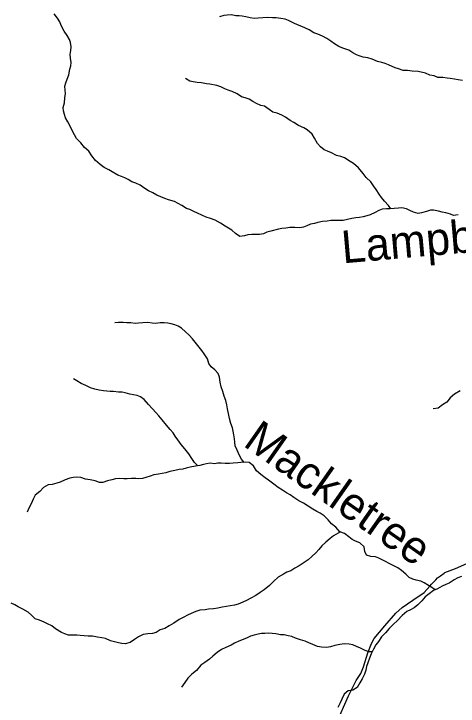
# Model space of a CAD drawing. Extents: x 0 to 34, y 0 to 22.
# Drawn here: x 3.475 to 4.768, y 15.178 to 17.193 of the extents above; entities that cross this region are included whole.
import ezdxf

# ---------------------------------------------------------------- set-up
doc = ezdxf.new("R2010")
doc.units = 0
for name, color, linetype in [('GM_X_Minor_River', 7, 'Continuous'), ('GM_X_Minor_River_Text', 7, 'Continuous'), ('GM_X_Township_Road', 7, 'Continuous')]:
    doc.layers.add(name, color=color, linetype=linetype)

msp = doc.modelspace()

# ---------------------------------------------------------------- linework, layer by layer
at = {"layer": 'GM_X_Minor_River'}
for points in [[(3.8433, 16.694), (3.8304, 16.6998), (3.8191, 16.704), (3.8081, 16.7102), (3.7986, 16.7152), (3.7884, 16.719), (3.7777, 16.7233), (3.7618, 16.7328), (3.7516, 16.7382), (3.738, 16.7455), (3.7262, 16.7543), (3.7134, 16.7662), (3.7021, 16.7791), (3.6938, 16.7925), (3.6809, 16.8036), (3.67, 16.8173), (3.6575, 16.8299), (3.6519, 16.8402), (3.6447, 16.8531), (3.638, 16.8672), (3.6327, 16.8779), (3.6256, 16.8901), (3.6226, 16.9), (3.62, 16.9106), (3.6193, 16.9201), (3.6224, 16.9338), (3.6241, 16.9486), (3.6257, 16.9607), (3.6246, 16.9706), (3.6239, 16.982), (3.6266, 16.9922), (3.6301, 17.0021), (3.6351, 17.0149), (3.6379, 17.0313), (3.6414, 17.0415), (3.6422, 17.0514), (3.6407, 17.0635), (3.6389, 17.0745), (3.6409, 17.0863), (3.6421, 17.0969), (3.6403, 17.1087), (3.6369, 17.1182), (3.6305, 17.1293), (3.6222, 17.1426), (3.6132, 17.1586), (3.6087, 17.1697), (3.6023, 17.1799), (3.5929, 17.1925)], [(4.0867, 17.1882), (4.0737, 17.1841)], [(4.7807, 16.9986), (4.7682, 17.0009), (4.7576, 17.0029), (4.7454, 17.0045), (4.7359, 17.0057), (4.7241, 17.0069), (4.7097, 17.0077), (4.6987, 17.0119), (4.6862, 17.0143), (4.6733, 17.0197), (4.652, 17.0251), (4.6349, 17.026), (4.6213, 17.0272), (4.6083, 17.0277), (4.5951, 17.0327), (4.5848, 17.035), (4.5659, 17.0442), (4.5564, 17.0477), (4.5465, 17.0508), (4.5332, 17.0539), (4.5184, 17.0604), (4.5055, 17.0647), (4.4923, 17.0667), (4.4828, 17.069), (4.4729, 17.0728), (4.4615, 17.0794), (4.4498, 17.0867), (4.4327, 17.0928), (4.4214, 17.0978), (4.4081, 17.1055), (4.3979, 17.1135), (4.3865, 17.1204), (4.3733, 17.1273), (4.3596, 17.1335), (4.3479, 17.1377), (4.3346, 17.1462), (4.3244, 17.1508), (4.313, 17.1558), (4.3005, 17.1604), (4.2903, 17.1654), (4.2751, 17.1731), (4.2652, 17.1773), (4.2523, 17.1793), (4.2383, 17.1805), (4.2284, 17.1813), (4.214, 17.1818), (4.1999, 17.1811), (4.1866, 17.1797), (4.1759, 17.1786), (4.1634, 17.1809), (4.1501, 17.1837), (4.1402, 17.186), (4.1307, 17.1868), (4.1212, 17.1869), (4.1091, 17.1892), (4.0962, 17.1889), (4.0867, 17.1882)], [(4.5728, 16.6254), (4.5652, 16.6352), (4.5539, 16.6471), (4.5452, 16.6581), (4.5384, 16.6681), (4.5294, 16.6814), (4.5218, 16.6921), (4.5139, 16.7035), (4.5011, 16.7165), (4.4924, 16.7283), (4.4785, 16.744), (4.4641, 16.7573), (4.4539, 16.7631), (4.4376, 16.7731), (4.4273, 16.7773), (4.4144, 16.7804), (4.3997, 16.7885), (4.3879, 16.7931), (4.3784, 16.7973), (4.3675, 16.8054), (4.3588, 16.8149), (4.3505, 16.8305), (4.3434, 16.8427), (4.3294, 16.8546), (4.3191, 16.8607), (4.3036, 16.868), (4.29, 16.876), (4.2794, 16.8826), (4.2657, 16.8918), (4.2548, 16.8979), (4.2419, 16.9033), (4.229, 16.9068), (4.218, 16.9144), (4.2044, 16.9236), (4.1945, 16.926), (4.1816, 16.9313), (4.171, 16.9379), (4.16, 16.944), (4.149, 16.9479), (4.138, 16.9506), (4.1251, 16.9598), (4.1111, 16.9663), (4.099, 16.9702), (4.0895, 16.9748), (4.0781, 16.9802), (4.0656, 16.984), (4.0459, 16.9879), (4.0356, 16.9888), (4.0219, 16.9915), (4.009, 16.9931), (3.9973, 16.9947), (3.9878, 16.9962), (3.9745, 17.0043)], [(4.7684, 16.6075), (4.7551, 16.6061), (4.7456, 16.6092), (4.7323, 16.6134), (4.7221, 16.615), (4.7111, 16.6185), (4.697, 16.6216), (4.6875, 16.6213), (4.6761, 16.6175), (4.6616, 16.6131), (4.6517, 16.612), (4.6388, 16.6158), (4.6278, 16.6208), (4.618, 16.6251), (4.6047, 16.6278), (4.5952, 16.6275), (4.5819, 16.6257), (4.5708, 16.6253), (4.5602, 16.625), (4.5473, 16.624), (4.5377, 16.6202), (4.5271, 16.6146), (4.5122, 16.6074), (4.5027, 16.6045), (4.4916, 16.6019), (4.4817, 16.6), (4.4703, 16.5993), (4.4589, 16.5967), (4.4467, 16.5938), (4.4338, 16.5916), (4.4243, 16.5912), (4.3977, 16.5914), (4.3874, 16.5895), (4.3737, 16.5881), (4.36, 16.5855), (4.3501, 16.5829), (4.3383, 16.5803), (4.328, 16.5755), (4.3185, 16.5721), (4.3071, 16.5703), (4.2934, 16.5711), (4.2782, 16.5704), (4.2672, 16.5693), (4.255, 16.5675), (4.2455, 16.5657), (4.2234, 16.5597), (4.2116, 16.5571), (4.202, 16.5526), (4.1899, 16.55), (4.1773, 16.5509), (4.1678, 16.5509), (4.156, 16.5495), (4.1465, 16.5465), (4.1328, 16.5443), (4.1203, 16.5538), (4.1097, 16.563), (4.0999, 16.5688), (4.09, 16.5749), (4.0772, 16.5837), (4.0609, 16.5918), (4.048, 16.5975), (4.0351, 16.6014), (4.0222, 16.6064), (4.0097, 16.613), (3.9991, 16.6176), (3.9873, 16.623), (3.9778, 16.626), (3.9638, 16.6349), (3.9532, 16.641), (3.9426, 16.6464), (3.9256, 16.6518), (3.9145, 16.6549), (3.9028, 16.6603), (3.8918, 16.6653), (3.8801, 16.6718), (3.8668, 16.6779), (3.8562, 16.6845), (3.8433, 16.694)], [(4.1458, 15.8875), (4.1379, 15.8968), (4.1308, 15.9097), (4.1251, 15.9227), (4.1199, 15.9356), (4.1181, 15.9459), (4.117, 15.9558), (4.1155, 15.9679), (4.1133, 15.9786), (4.1115, 15.9881), (4.1066, 16.001), (4.1033, 16.0147), (4.1007, 16.025), (4.097, 16.0428), (4.0952, 16.0546), (4.0918, 16.0676), (4.0877, 16.0797), (4.0832, 16.0934), (4.0791, 16.1071), (4.0758, 16.1212), (4.0736, 16.1356), (4.0695, 16.1463), (4.0601, 16.1566), (4.0495, 16.165), (4.0427, 16.1749), (4.0386, 16.189), (4.0292, 16.2031), (4.022, 16.2126), (4.0145, 16.2222), (4.0066, 16.2321), (3.9953, 16.247), (3.9851, 16.2577), (3.9749, 16.2676), (3.9635, 16.2775), (3.9537, 16.284), (3.9442, 16.2879), (3.9328, 16.2906), (3.9233, 16.2922), (3.9127, 16.293), (3.9009, 16.2934), (3.8876, 16.292), (3.8777, 16.2928), (3.8652, 16.294), (3.8507, 16.2937), (3.8378, 16.2923), (3.8283, 16.292), (3.8157, 16.2932), (3.804, 16.2936), (3.7937, 16.2941), (3.78, 16.2945), (3.7697, 16.2934)], [(4.0104, 15.8774), (4.0014, 15.8869), (3.9931, 15.8991), (3.9848, 15.9125), (3.9731, 15.9266), (3.9625, 15.9399), (3.9524, 15.9529), (3.9452, 15.964), (3.9388, 15.9735), (3.9301, 15.9834), (3.9192, 15.9956), (3.9071, 16.0113), (3.8977, 16.0231), (3.8886, 16.0326), (3.8788, 16.0429), (3.8671, 16.0559), (3.8543, 16.07), (3.844, 16.0777), (3.8346, 16.0823), (3.8236, 16.0835), (3.8133, 16.0855), (3.7996, 16.0893), (3.7902, 16.0913), (3.7795, 16.0914), (3.7655, 16.0941), (3.756, 16.0941), (3.7461, 16.0946), (3.7366, 16.0954), (3.7237, 16.0974), (3.7111, 16.1005), (3.6982, 16.104), (3.6846, 16.1109), (3.6717, 16.1167), (3.6588, 16.1247), (3.6494, 16.1301)], [(4.774, 16.0956), (4.7575, 16.0858), (4.7453, 16.0749), (4.7354, 16.0631), (4.7231, 16.0545), (4.7102, 16.0454), (4.6961, 16.0429)], [(4.7013, 15.5169), (4.6917, 15.5238), (4.6822, 15.5292), (4.669, 15.5368), (4.6595, 15.5414), (4.6462, 15.5446), (4.636, 15.5473), (4.6257, 15.5526), (4.6163, 15.5622), (4.6031, 15.5729), (4.5925, 15.5806), (4.5796, 15.5878), (4.5674, 15.5928), (4.5572, 15.5994), (4.547, 15.604), (4.5371, 15.6086), (4.5277, 15.6124), (4.5147, 15.614), (4.5018, 15.6175), (4.497, 15.6278), (4.4948, 15.6419), (4.4827, 15.6529), (4.4698, 15.6583), (4.4603, 15.6629), (4.4505, 15.671), (4.4372, 15.6802), (4.4243, 15.6856), (4.4119, 15.6985), (4.4002, 15.7085), (4.3896, 15.7207), (4.3786, 15.7321), (4.3669, 15.7398), (4.3574, 15.7444), (4.3457, 15.7513), (4.3317, 15.7601), (4.318, 15.7689), (4.3048, 15.7755), (4.2904, 15.785), (4.279, 15.7927), (4.2688, 15.7985), (4.2567, 15.8061), (4.2446, 15.8142), (4.2317, 15.8245), (4.2166, 15.836), (4.2067, 15.8429), (4.1943, 15.852), (4.1814, 15.8631), (4.1727, 15.8769), (4.1603, 15.8872), (4.15, 15.8876), (4.1363, 15.8873), (4.1268, 15.8862), (4.1139, 15.8848), (4.1032, 15.8837), (4.0899, 15.8845), (4.0789, 15.885), (4.0694, 15.8847), (4.0591, 15.8836), (4.0462, 15.8848), (4.0363, 15.8833), (4.0268, 15.8815), (4.0169, 15.8785), (4.004, 15.8763), (3.9884, 15.8737), (3.9769, 15.8704), (3.9667, 15.8678), (3.9568, 15.8663), (3.9442, 15.8637), (3.9297, 15.8611), (3.9172, 15.857), (3.9073, 15.8548), (3.8959, 15.8534), (3.8829, 15.8512), (3.8723, 15.8474), (3.8597, 15.8433), (3.8502, 15.8403), (3.8395, 15.84), (3.83, 15.8404), (3.8175, 15.8409), (3.8053, 15.8394), (3.7954, 15.8395), (3.7814, 15.8403), (3.7711, 15.8393), (3.7608, 15.8367), (3.7475, 15.8333), (3.7345, 15.8292), (3.725, 15.8289), (3.7121, 15.8339), (3.6973, 15.837), (3.6837, 15.839), (3.6704, 15.8432), (3.6586, 15.8448), (3.648, 15.8438), (3.6381, 15.8415), (3.6247, 15.8363), (3.6102, 15.8295), (3.6007, 15.8269), (3.587, 15.8232), (3.5756, 15.8221), (3.5615, 15.8142), (3.5508, 15.8025)], [(3.5508, 15.8025), (3.5378, 15.792), (3.532, 15.7806), (3.5255, 15.767), (3.5189, 15.7545), (3.5143, 15.7427)], [(4.4256, 15.685), (4.419, 15.6818), (4.4053, 15.6739), (4.3957, 15.666), (4.3831, 15.655), (4.3712, 15.6445), (4.3628, 15.6343), (4.3544, 15.6244), (4.3425, 15.6139), (4.3315, 15.6041), (4.3177, 15.5943), (4.3055, 15.5867), (4.2929, 15.58), (4.2811, 15.5721), (4.27, 15.5683), (4.2601, 15.5623), (4.2445, 15.5537), (4.2319, 15.5416), (4.2192, 15.5291), (4.2039, 15.5167), (4.1917, 15.5084), (4.1795, 15.5005), (4.1654, 15.4926), (4.1524, 15.4858), (4.1414, 15.4802), (4.1284, 15.4746), (4.1174, 15.4724), (4.1044, 15.4698), (4.0942, 15.4679), (4.0816, 15.4665), (4.0694, 15.4635), (4.0561, 15.4609), (4.042, 15.4599), (4.0325, 15.4588), (4.0162, 15.457), (4.0047, 15.4533), (3.9918, 15.4473), (3.9807, 15.4424), (3.9697, 15.4367), (3.9563, 15.43), (3.9407, 15.4191), (3.9277, 15.4115), (3.9143, 15.4044), (3.9014, 15.3999), (3.8899, 15.3924), (3.8785, 15.3894), (3.8656, 15.3887), (3.8519, 15.3865), (3.8378, 15.3794), (3.8263, 15.3719), (3.8134, 15.3632), (3.7996, 15.3591), (3.7894, 15.3607), (3.7795, 15.3626), (3.7678, 15.365), (3.7571, 15.3681), (3.742, 15.375), (3.7317, 15.3766), (3.7184, 15.3793), (3.7044, 15.3813), (3.6914, 15.3814), (3.6801, 15.3826), (3.6687, 15.3834), (3.6588, 15.3842), (3.644, 15.3847), (3.6344, 15.3847), (3.6234, 15.3886), (3.6136, 15.3928), (3.5969, 15.4032), (3.5863, 15.4116), (3.5735, 15.4177), (3.5636, 15.422), (3.5496, 15.4281), (3.5374, 15.4324), (3.5272, 15.4427), (3.5166, 15.4515), (3.5015, 15.4603), (3.4879, 15.4672), (3.478, 15.473), (3.4674, 15.478)], [(4.7782, 15.5556), (4.7671, 15.5518), (4.7565, 15.5458), (4.7419, 15.5357), (4.7324, 15.5319), (4.7221, 15.527), (4.7084, 15.5195), (4.6962, 15.515), (4.684, 15.5048), (4.6728, 15.4964), (4.6626, 15.4848), (4.6511, 15.4731), (4.64, 15.4641), (4.6301, 15.4584), (4.6187, 15.4536), (4.6057, 15.4423), (4.5919, 15.4271), (4.5796, 15.4158), (4.5674, 15.4037), (4.5571, 15.3913), (4.5456, 15.3799), (4.5364, 15.3663), (4.5287, 15.3561), (4.5218, 15.3436), (4.5152, 15.3304), (4.5106, 15.3179), (4.5052, 15.3046), (4.5021, 15.2932), (4.4997, 15.2826), (4.4959, 15.2709), (4.4893, 15.258), (4.4824, 15.2455), (4.4747, 15.2322), (4.4621, 15.2247), (4.4481, 15.2229), (4.437, 15.2127), (4.4297, 15.1983), (4.4246, 15.1877), (4.4185, 15.1741)], [(4.5182, 15.3363), (4.5092, 15.3361), (4.4974, 15.34), (4.4838, 15.3469), (4.4724, 15.3519), (4.4622, 15.3569), (4.4512, 15.3588), (4.4375, 15.3597), (4.4242, 15.3571), (4.4097, 15.3541), (4.3964, 15.3504), (4.3857, 15.3486), (4.3705, 15.3498), (4.3595, 15.3521), (4.3455, 15.3571), (4.3341, 15.3625), (4.3228, 15.3675), (4.3095, 15.371), (4.2954, 15.376), (4.2841, 15.3803), (4.2738, 15.3826), (4.2617, 15.3853), (4.2518, 15.3858), (4.2377, 15.3881), (4.2267, 15.3897), (4.2172, 15.3905), (4.2058, 15.3898), (4.1963, 15.3895), (4.186, 15.3873), (4.1746, 15.3851), (4.164, 15.3817), (4.1544, 15.3768), (4.143, 15.372), (4.13, 15.3671), (4.1171, 15.3611), (4.1075, 15.3551), (4.0927, 15.3483), (4.0801, 15.3427), (4.0671, 15.3344), (4.0549, 15.3239), (4.0446, 15.3148), (4.0316, 15.3054), (4.0197, 15.2971), (4.0071, 15.282), (3.9937, 15.271), (3.9819, 15.2593), (3.973, 15.2469), (3.9635, 15.2336)]]:
    msp.add_lwpolyline(points, dxfattribs=at)
at = {"layer": 'GM_X_Township_Road'}
for points in [[(4.7277, 15.5653), (4.73, 15.567), (4.7609, 15.5786), (4.8026, 15.5966)], [(4.691, 15.5328), (4.703, 15.5461), (4.7087, 15.5512), (4.7167, 15.5571), (4.7277, 15.5653)], [(4.4135, 15.127), (4.4497, 15.2084), (4.4719, 15.2523), (4.4852, 15.2734), (4.4929, 15.2923), (4.5051, 15.3336), (4.5164, 15.3605), (4.5239, 15.3747), (4.5547, 15.4118), (4.5867, 15.4486), (4.6059, 15.465), (4.6365, 15.4865), (4.6694, 15.5088), (4.6864, 15.5276), (4.691, 15.5328)]]:
    msp.add_lwpolyline(points, dxfattribs=at)

# ---------------------------------------------------------------- texts
at = {"layer": 'GM_X_Minor_River_Text'}
for s, height, rotation, p in [('Lampblack', 0.09469, 5.0007, (4.4328, 16.4664)), ('Mackletree', 0.0947, 324.9998, (4.1393, 15.9374))]:
    msp.add_text(s, height=height, rotation=rotation, dxfattribs=at).set_placement(p)

doc.saveas('drawing.dxf')
